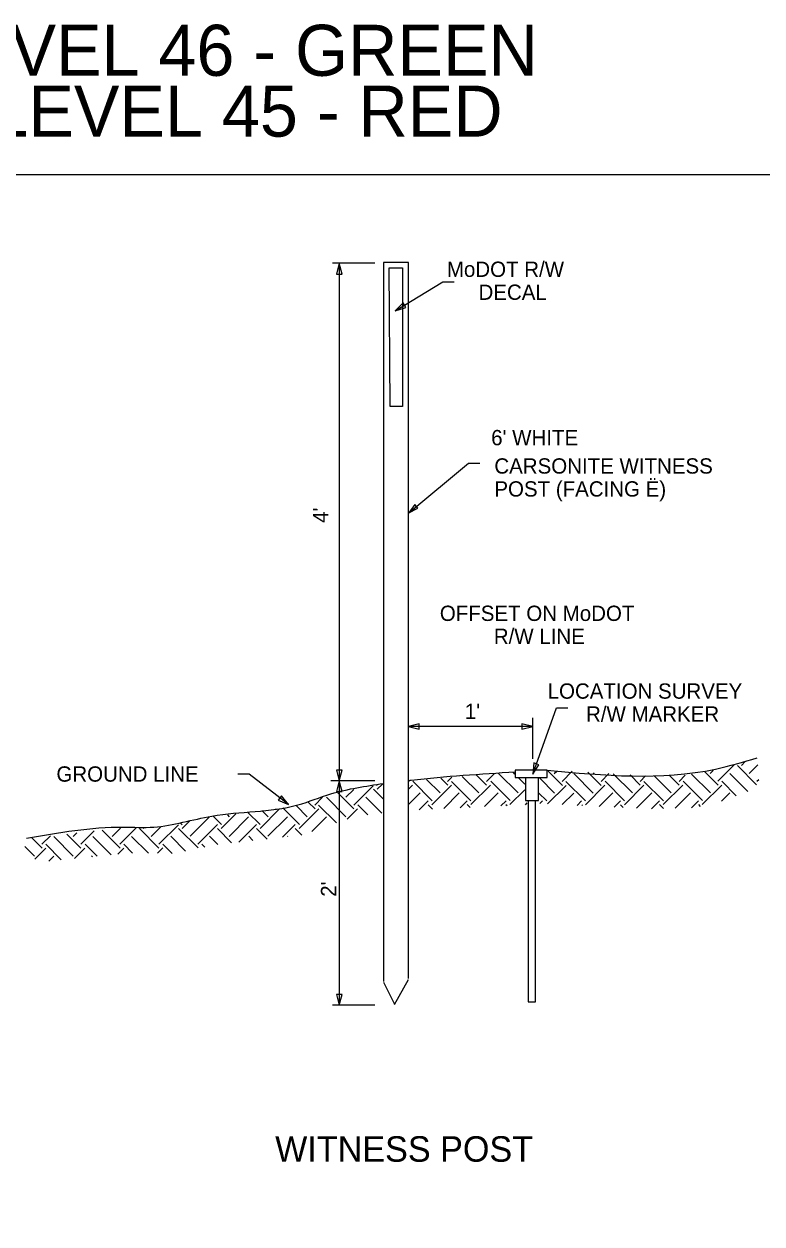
# Model space of a CAD drawing. Extents: x -439.1 to -407.9, y -458.1 to -436.2.
# Drawn here: x -425.53 to -418.31, y -447.96 to -436.2 of the extents above; entities that cross this region are included whole.
import ezdxf

# ---------------------------------------------------------------- set-up
doc = ezdxf.new("R2010")
doc.units = 0
for name, color, linetype in [('Bridge-Named Boundary', 7, 'Continuous'), ('Level 4', 7, 'Continuous'), ('Level 45', 7, 'Continuous'), ('Level 46', 7, 'Continuous')]:
    doc.layers.add(name, color=color, linetype=linetype)

msp = doc.modelspace()

# ---------------------------------------------------------------- linework, layer by layer
at = {"layer": 'Bridge-Named Boundary'}
msp.add_lwpolyline([(-439.109, -458.051), (-407.859, -458.051), (-407.859, -437.676), (-439.109, -437.676)], close=True, dxfattribs=at)
at = {"layer": 'Level 4'}
for p, q in [((-422.098, -438.542), (-422.513, -438.542)), ((-422.447, -438.542), (-422.447, -445.813)), ((-422.014, -438.534), (-422.014, -445.582)), ((-421.77, -438.534), (-422.014, -438.534)), ((-421.77, -445.553), (-421.77, -438.534)), ((-421.958, -438.588), (-421.826, -438.588)), ((-421.947, -439.947), (-421.958, -438.588)), ((-421.826, -438.588), (-421.826, -439.947)), ((-421.826, -439.947), (-421.947, -439.947)), ((-420.552, -443.399), (-420.552, -442.999)), ((-420.552, -443.083), (-421.77, -443.083)), ((-418.738, -443.619), (-418.575, -443.456)), ((-418.547, -443.466), (-418.36, -443.653)), ((-418.509, -443.466), (-418.47, -443.427)), ((-418.432, -443.542), (-418.349, -443.459)), ((-422.098, -443.615), (-422.53, -443.615)), ((-421.767, -443.621), (-421.762, -443.615)), ((-421.727, -443.619), (-421.536, -443.81)), ((-421.593, -443.601), (-421.46, -443.734)), ((-421.452, -443.589), (-421.383, -443.658)), ((-421.386, -443.62), (-421.346, -443.58)), ((-421.348, -443.62), (-421.157, -443.811)), ((-421.243, -443.572), (-421.08, -443.734)), ((-421.102, -443.56), (-421.004, -443.658)), ((-421.004, -443.62), (-420.929, -443.545)), ((-420.964, -443.618), (-420.773, -443.809)), ((-420.888, -443.542), (-420.696, -443.733)), ((-420.747, -443.53), (-420.729, -443.548)), ((-420.723, -443.511), (-420.723, -443.582)), ((-420.411, -443.511), (-420.723, -443.511)), ((-420.723, -443.582), (-420.411, -443.582)), ((-420.69, -443.587), (-420.629, -443.647)), ((-420.624, -443.582), (-420.624, -443.809)), ((-420.496, -443.809), (-420.496, -443.582)), ((-420.484, -443.59), (-420.339, -443.735)), ((-420.411, -443.582), (-420.411, -443.511)), ((-420.401, -443.52), (-420.262, -443.659)), ((-420.341, -443.544), (-420.317, -443.52)), ((-420.264, -443.621), (-420.165, -443.521)), ((-420.227, -443.621), (-420.035, -443.812)), ((-420.15, -443.544), (-419.959, -443.735)), ((-420.011, -443.531), (-419.883, -443.659)), ((-419.959, -443.544), (-419.949, -443.535)), ((-419.883, -443.621), (-419.806, -443.544)), ((-419.843, -443.619), (-419.652, -443.81)), ((-419.763, -443.547), (-419.575, -443.734)), ((-419.599, -443.557), (-419.499, -443.658)), ((-419.501, -443.62), (-419.448, -443.567)), ((-419.463, -443.62), (-419.272, -443.811)), ((-419.361, -443.569), (-419.196, -443.734)), ((-419.214, -443.563), (-419.119, -443.658)), ((-419.119, -443.62), (-419.058, -443.558)), ((-419.08, -443.618), (-418.888, -443.809)), ((-418.996, -443.549), (-418.812, -443.733)), ((-418.865, -443.527), (-418.735, -443.657)), ((-418.814, -443.542), (-418.785, -443.513)), ((-418.7, -443.619), (-418.558, -443.761)), ((-418.623, -443.542), (-418.446, -443.719)), ((-418.356, -443.619), (-418.338, -443.601)), ((-422.46, -443.734), (-422.304, -443.89)), ((-422.381, -443.776), (-422.305, -443.7)), ((-422.304, -443.852), (-422.115, -443.663)), ((-422.112, -443.698), (-422.017, -443.792)), ((-422.08, -443.656), (-422.075, -443.661)), ((-422.076, -443.698), (-422.024, -443.646)), ((-421.768, -443.695), (-421.73, -443.658)), ((-421.768, -443.658), (-421.767, -443.659)), ((-421.768, -443.848), (-421.653, -443.734)), ((-421.539, -443.849), (-421.347, -443.658)), ((-421.423, -443.887), (-421.271, -443.734)), ((-421.158, -443.848), (-420.967, -443.657)), ((-421.025, -443.868), (-420.89, -443.733)), ((-420.775, -443.848), (-420.629, -443.702)), ((-420.494, -443.733), (-420.415, -443.811)), ((-420.409, -443.841), (-420.226, -443.659)), ((-420.263, -443.848), (-420.15, -443.735)), ((-420.036, -443.849), (-419.846, -443.658)), ((-419.9, -443.865), (-419.769, -443.734)), ((-419.654, -443.849), (-419.463, -443.658)), ((-419.535, -443.882), (-419.386, -443.734)), ((-419.273, -443.848), (-419.082, -443.657)), ((-419.156, -443.883), (-419.006, -443.733)), ((-418.891, -443.848), (-418.7, -443.657)), ((-418.704, -443.815), (-418.623, -443.733)), ((-422.866, -443.861), (-422.761, -443.967)), ((-422.751, -443.823), (-422.684, -443.89)), ((-422.686, -443.852), (-422.611, -443.776)), ((-422.649, -443.852), (-422.473, -444.027)), ((-422.572, -443.775), (-422.381, -443.967)), ((-422.265, -443.851), (-422.166, -443.949)), ((-422.188, -443.774), (-422.03, -443.933)), ((-421.664, -443.898), (-421.577, -443.811)), ((-421.577, -443.849), (-421.534, -443.892)), ((-421.263, -443.879), (-421.195, -443.81)), ((-421.193, -443.848), (-421.166, -443.875)), ((-420.864, -443.861), (-420.813, -443.81)), ((-420.814, -443.848), (-420.804, -443.858)), ((-420.624, -443.809), (-420.496, -443.809)), ((-420.624, -443.849), (-420.606, -443.832)), ((-420.597, -443.809), (-420.597, -445.78)), ((-420.524, -445.78), (-420.524, -443.809)), ((-420.482, -443.838), (-420.456, -443.812)), ((-420.117, -443.855), (-420.074, -443.811)), ((-420.072, -443.849), (-420.063, -443.858)), ((-419.754, -443.872), (-419.692, -443.811)), ((-419.693, -443.849), (-419.665, -443.876)), ((-419.389, -443.889), (-419.31, -443.81)), ((-419.309, -443.848), (-419.27, -443.887)), ((-418.997, -443.878), (-418.929, -443.81)), ((-418.929, -443.848), (-418.912, -443.866)), ((-423.908, -444.158), (-423.722, -443.972)), ((-423.678, -443.966), (-423.6, -444.044)), ((-423.603, -444.082), (-423.46, -443.939)), ((-423.542, -443.949), (-423.524, -443.968)), ((-423.526, -444.159), (-423.335, -443.968)), ((-423.341, -443.924), (-423.221, -444.044)), ((-423.222, -444.081), (-423.031, -443.89)), ((-423.205, -443.907), (-423.144, -443.968)), ((-423.145, -444.157), (-422.954, -443.967)), ((-423.07, -443.89), (-423.068, -443.891)), ((-422.999, -443.881), (-422.837, -444.043)), ((-422.839, -444.081), (-422.648, -443.89)), ((-422.717, -444.112), (-422.572, -443.967)), ((-422.369, -443.991), (-422.267, -443.889)), ((-424.769, -444.098), (-424.593, -444.274)), ((-424.672, -444.159), (-424.591, -444.079)), ((-424.595, -444.236), (-424.436, -444.077)), ((-424.405, -444.083), (-424.213, -444.274)), ((-424.366, -444.083), (-424.36, -444.077)), ((-424.29, -444.16), (-424.192, -444.062)), ((-424.213, -444.236), (-424.022, -444.045)), ((-424.021, -444.082), (-423.829, -444.273)), ((-424.004, -444.025), (-423.984, -444.045)), ((-423.985, -444.082), (-423.909, -444.006)), ((-423.832, -444.235), (-423.641, -444.044)), ((-423.641, -444.082), (-423.501, -444.223)), ((-423.43, -444.215), (-423.259, -444.044)), ((-423.257, -444.081), (-423.154, -444.185)), ((-423.002, -444.168), (-422.878, -444.043)), ((-422.878, -444.081), (-422.813, -444.146)), ((-425.458, -444.174), (-425.356, -444.275)), ((-425.359, -444.237), (-425.275, -444.153)), ((-425.244, -444.16), (-425.053, -444.352)), ((-425.116, -444.136), (-424.977, -444.275)), ((-425.053, -444.161), (-425.017, -444.125)), ((-424.977, -444.237), (-424.846, -444.106)), ((-424.861, -444.159), (-424.68, -444.34)), ((-424.481, -444.159), (-424.316, -444.324)), ((-424.097, -444.158), (-423.952, -444.304)), ((-423.717, -444.158), (-423.636, -444.24)), ((-423.334, -444.157), (-423.292, -444.2)), ((-422.954, -444.157), (-422.949, -444.162)), ((-425.527, -444.258), (-425.433, -444.352)), ((-425.429, -444.384), (-425.32, -444.275)), ((-425.321, -444.237), (-425.169, -444.389)), ((-425.041, -444.376), (-424.94, -444.274)), ((-424.937, -444.236), (-424.819, -444.354)), ((-424.617, -444.334), (-424.557, -444.274)), ((-424.557, -444.236), (-424.471, -444.323)), ((-424.228, -444.325), (-424.176, -444.273)), ((-424.174, -444.235), (-424.082, -444.326)), ((-423.794, -444.235), (-423.763, -444.266)), ((-425.293, -444.401), (-425.244, -444.352)), ((-424.871, -444.359), (-424.863, -444.351)), ((-422.014, -445.588), (-421.905, -445.805)), ((-421.905, -445.807), (-421.77, -445.563)), ((-422.098, -445.813), (-422.513, -445.813)), ((-420.597, -445.78), (-420.524, -445.78))]:
    msp.add_line(p, q, dxfattribs=at)
for points in [[(-422.42, -438.648), (-422.447, -438.542), (-422.473, -438.648)], [(-421.822, -438.93), (-421.899, -439.008), (-421.794, -438.976)], [(-421.707, -440.908), (-421.766, -440.987), (-421.676, -440.944)], [(-421.664, -443.056), (-421.77, -443.083), (-421.664, -443.109)], [(-420.658, -443.109), (-420.552, -443.083), (-420.658, -443.056)], [(-422.473, -443.509), (-422.447, -443.615), (-422.42, -443.509)], [(-420.542, -443.44), (-420.552, -443.548), (-420.492, -443.458)], [(-422.42, -443.721), (-422.447, -443.615), (-422.473, -443.721)], [(-423.045, -443.803), (-422.945, -443.848), (-423.012, -443.762)], [(-422.473, -445.708), (-422.447, -445.813), (-422.42, -445.708)]]:
    msp.add_lwpolyline(points, close=True, dxfattribs=at)
for points in [[(-421.899, -439.008), (-421.433, -438.725), (-421.321, -438.725)], [(-421.766, -440.987), (-421.182, -440.502), (-421.069, -440.502)], [(-420.552, -443.548), (-420.32, -442.9), (-420.207, -442.9)], [(-422.945, -443.848), (-423.328, -443.548), (-423.44, -443.548)]]:
    msp.add_lwpolyline(points, dxfattribs=at)
for points in [[(-420.411, -443.511), (-418.761, -443.499), (-418.355, -443.39)], [(-421.77, -443.61), (-421.743, -443.607), (-420.723, -443.526)], [(-425.51, -444.177), (-424.562, -444.068), (-424.263, -444.068), (-423.694, -443.96), (-422.854, -443.851), (-422.529, -443.743), (-422.014, -443.641)]]:
    msp.add_spline(points, degree=3, dxfattribs=at)

# ---------------------------------------------------------------- texts
for s, height, p in [('MoDOT R/W', 0.15, (-421.393, -438.676)), ('DECAL', 0.15, (-421.083, -438.901)), ('CARSONITE WITNESS', 0.15, (-420.928, -440.604)), ('POST (FACING Ë)', 0.15, (-420.928, -440.829)), ('OFFSET ON MoDOT', 0.15, (-421.462, -442.048)), ('R/W LINE', 0.15, (-420.933, -442.273)), ('LOCATION SURVEY', 0.15, (-420.406, -442.81)), ('R/W MARKER', 0.15, (-420.03, -443.035)), ('GROUND LINE', 0.15, (-425.217, -443.623)), ('WITNESS POST', 0.25, (-423.075, -447.348))]:
    msp.add_text(s, height=height, dxfattribs=at).set_placement(p)
at = {"layer": 'Level 45'}
for s, height, p in [('ENGLISH - LEVEL 45 - RED', 0.5, (-429.393, -437.301)), ("6' WHITE", 0.15, (-420.959, -440.326)), ("1'", 0.15, (-421.217, -443.008))]:
    msp.add_text(s, height=height, dxfattribs=at).set_placement(p)
for s, p in [("4'", (-422.555, -441.087)), ("2'", (-422.477, -444.751))]:
    msp.add_text(s, height=0.15, rotation=90, dxfattribs=at).set_placement(p)
at = {"layer": 'Level 46'}
msp.add_text('METRIC - LEVEL 46 - GREEN', height=0.5, dxfattribs=at).set_placement((-429.642, -436.705))

doc.saveas('drawing.dxf')
